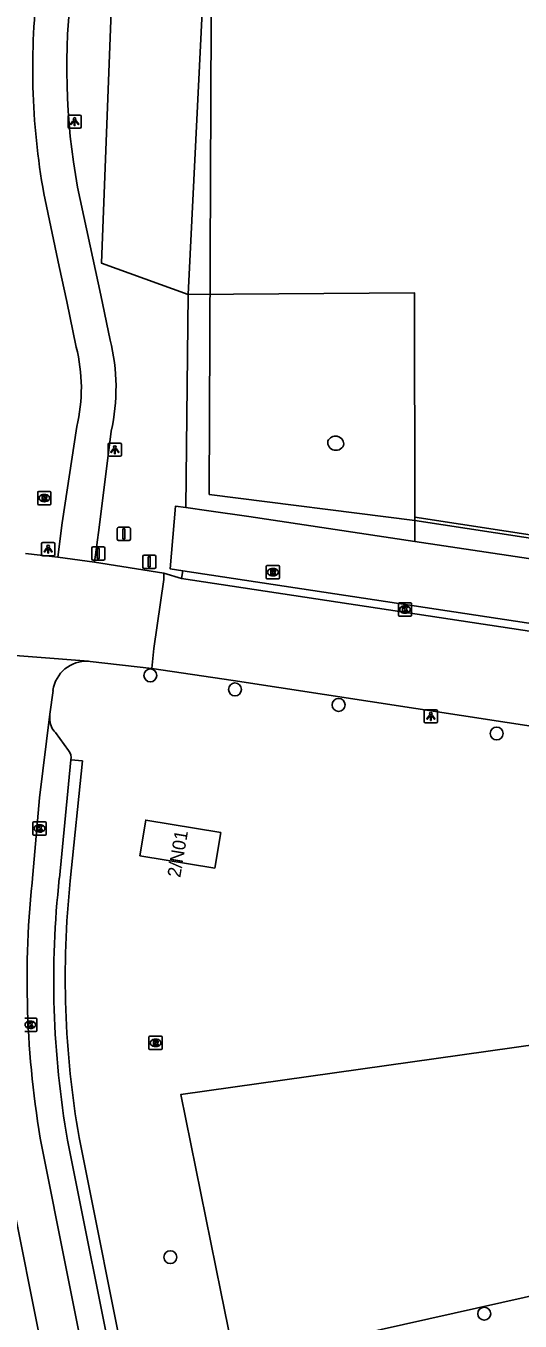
# Model space of a CAD drawing. Extents: x 160203 to 161526, y 379529 to 381797.
# Drawn here: x 160816.3 to 160853.7, y 380497.8 to 380595.6 of the extents above; entities that cross this region are included whole.
import ezdxf

# ---------------------------------------------------------------- set-up
doc = ezdxf.new("R2010")
doc.units = 0
for name, color, linetype in [('IMGEO_Boom', 7, 'Continuous'), ('IMGEO_Fietspad_open', 7, 'Continuous'), ('IMGEO_Gemengd_bos', 7, 'Continuous'), ('IMGEO_Hek', 7, 'Continuous'), ('IMGEO_Kolk', 7, 'Continuous'), ('IMGEO_Lichtpunt', 7, 'Continuous'), ('IMGEO_Loofbos', 7, 'Continuous'), ('IMGEO_Opslagtank', 7, 'Continuous'), ('IMGEO_Pand', 7, 'Continuous'), ('IMGEO_Pand_nummerreeks', 7, 'Continuous'), ('IMGEO_Parkeervlak_gesloten', 7, 'Continuous'), ('IMGEO_Parkeervlak_open', 7, 'Continuous'), ('IMGEO_Rijbaan_lokaal_gesloten', 7, 'Continuous'), ('IMGEO_Rijbaan_lokaal_open', 7, 'Continuous'), ('IMGEO_Rioolput', 7, 'Continuous'), ('IMGEO_Verkeersbordpaal', 7, 'Continuous'), ('IMGEO_Vlaggenmast', 7, 'Continuous'), ('IMGEO_Voetpad_open', 7, 'Continuous')]:
    doc.layers.add(name, color=color, linetype=linetype)

msp = doc.modelspace()

# ---------------------------------------------------------------- linework, layer by layer
at = {"layer": 'IMGEO_Boom'}
for centre in [(160825.731, 380546.573), (160832.132, 380545.511), (160839.97, 380544.344), (160851.927, 380542.182), (160827.24, 380502.618), (160850.985, 380498.346)]:
    msp.add_circle(centre, 0.489, dxfattribs=at)
at = {"layer": 'IMGEO_Fietspad_open'}
for points in [[(160820.125, 380571.38), (160819.419, 380574.816), (160818.832, 380577.453), (160817.677, 380582.969)], [(160822.69, 380571.911), (160821.975, 380575.301), (160821.373, 380578.101), (160820.223, 380583.465)], [(160818.72, 380555.51), (160819.05, 380558.09), (160820.171, 380565.369)], [(160821.515, 380555.129), (160821.858, 380557.745), (160822.774, 380565.019)]]:
    msp.add_lwpolyline(points, dxfattribs=at)
for centre, radius, start, end in [((160869.954, 380592.425), 53.126, 172.76167, 190.25321), ((160869.742, 380592.476), 50.332, 172.68835, 190.31381), ((160808.088, 380568.287), 15.045, 347.4561, 13.94048), ((160807.852, 380568.28), 12.658, 346.70262, 14.17429)]:
    msp.add_arc(centre, radius, start, end, dxfattribs=at)
at = {"layer": 'IMGEO_Gemengd_bos'}
for points in [[(160828.587, 380575.341), (160822.037, 380577.708), (160823.148, 380606.566), (160823.194, 380607.805)], [(160830.151, 380607.923), (160830.156, 380606.87), (160828.587, 380575.341)], [(160828.405, 380559.25), (160828.587, 380575.341)], [(160828.587, 380575.341), (160845.706, 380575.486), (160845.74, 380558.527)], [(160845.74, 380558.527), (160910.065, 380548.671), (160940.334, 380544.69)], [(160845.744, 380556.692), (160845.74, 380558.527)]]:
    msp.add_lwpolyline(points, dxfattribs=at)
at = {"layer": 'IMGEO_Hek'}
for points in [[(160830.403, 380613.941), (160830.181, 380560.25)], [(160845.741, 380558.276), (160830.181, 380560.25)], [(160964.899, 380552.777), (160964.896, 380551.38), (160959.504, 380551), (160940.157, 380543.996), (160899.412, 380550.147), (160882.829, 380552.68), (160868.014, 380554.875), (160845.741, 380558.276)], [(160855.926, 380500), (160832.145, 380494.674)]]:
    msp.add_lwpolyline(points, dxfattribs=at)
at = {"layer": 'IMGEO_Kolk'}
for p, q in [((160844.494, 380551.124), (160844.494, 380551.976)), ((160844.569, 380552.05), (160845.421, 380552.05)), ((160845.005, 380551.27), (160844.98, 380551.27)), ((160844.982, 380551.83), (160845.007, 380551.83)), ((160845.495, 380551.976), (160845.495, 380551.124)), ((160845.421, 380551.05), (160844.569, 380551.05)), ((160816.849, 380534.584), (160816.849, 380535.436)), ((160816.924, 380535.51), (160817.776, 380535.51)), ((160817.36, 380534.73), (160817.335, 380534.73)), ((160817.337, 380535.29), (160817.362, 380535.29)), ((160817.85, 380535.436), (160817.85, 380534.584)), ((160817.776, 380534.51), (160816.924, 380534.51)), ((160816.224, 380520.676), (160817.076, 380520.676)), ((160816.66, 380519.896), (160816.635, 380519.896)), ((160816.637, 380520.456), (160816.662, 380520.456)), ((160817.15, 380520.602), (160817.15, 380519.75)), ((160817.076, 380519.676), (160816.224, 380519.676))]:
    msp.add_line(p, q, dxfattribs=at)
for points in [[(160844.494, 380551.124), (160844.494, 380551.976)], [(160844.569, 380552.05), (160845.421, 380552.05)], [(160844.815, 380551.75), (160844.938, 380551.75), (160844.938, 380551.599), (160845.068, 380551.75), (160845.232, 380551.75), (160845.086, 380551.599), (160845.239, 380551.35), (160845.087, 380551.35), (160845.002, 380551.514), (160844.938, 380551.447), (160844.938, 380551.35), (160844.815, 380551.35), (160844.815, 380551.75)], [(160845.495, 380551.976), (160845.495, 380551.124)], [(160845.421, 380551.05), (160844.569, 380551.05)], [(160816.849, 380534.584), (160816.849, 380535.436)], [(160816.924, 380535.51), (160817.776, 380535.51)], [(160817.17, 380535.21), (160817.293, 380535.21), (160817.293, 380535.059), (160817.423, 380535.21), (160817.587, 380535.21), (160817.441, 380535.059), (160817.594, 380534.81), (160817.442, 380534.81), (160817.357, 380534.974), (160817.293, 380534.907), (160817.293, 380534.81), (160817.17, 380534.81), (160817.17, 380535.21)], [(160817.85, 380535.436), (160817.85, 380534.584)], [(160817.776, 380534.51), (160816.924, 380534.51)], [(160816.224, 380520.676), (160817.076, 380520.676)], [(160816.47, 380520.376), (160816.593, 380520.376), (160816.593, 380520.225), (160816.723, 380520.376), (160816.887, 380520.376), (160816.741, 380520.225), (160816.894, 380519.976), (160816.742, 380519.976), (160816.657, 380520.14), (160816.593, 380520.073), (160816.593, 380519.976), (160816.47, 380519.976), (160816.47, 380520.376)], [(160817.15, 380520.602), (160817.15, 380519.75)], [(160817.076, 380519.676), (160816.224, 380519.676)]]:
    msp.add_lwpolyline(points, dxfattribs=at)
for centre, start, end in [((160844.571, 380551.974), 91.55205, 178.44795), ((160844.571, 380551.974), 91.55205, 178.44795), ((160845.419, 380551.974), 1.55205, 88.44795), ((160845.419, 380551.974), 1.55205, 88.44795), ((160844.571, 380551.126), 181.55205, 268.44795), ((160844.571, 380551.126), 181.55205, 268.44795), ((160845.419, 380551.126), 271.55205, 358.44795), ((160845.419, 380551.126), 271.55205, 358.44795), ((160816.926, 380535.434), 91.55205, 178.44795), ((160816.926, 380535.434), 91.55205, 178.44795), ((160816.926, 380534.586), 181.55205, 268.44795), ((160816.926, 380534.586), 181.55205, 268.44795), ((160817.774, 380535.434), 1.55205, 88.44795), ((160817.774, 380535.434), 1.55205, 88.44795), ((160817.774, 380534.586), 271.55205, 358.44795), ((160817.774, 380534.586), 271.55205, 358.44795), ((160817.074, 380520.6), 1.55205, 88.44795), ((160817.074, 380520.6), 1.55205, 88.44795), ((160817.074, 380519.752), 271.55205, 358.44795), ((160817.074, 380519.752), 271.55205, 358.44795)]:
    msp.add_arc(centre, 0.0765, start, end, dxfattribs=at)
for centre, major_axis, ratio, start_param, end_param in [((160844.981, 380551.55), (-0.387, 0.002), 0.722429, 4.712389, 7.853982), ((160845.006, 380551.55), (-0.39, 0.002), 0.717154, 1.570796, 4.712389), ((160817.336, 380535.01), (-0.387, 0.002), 0.722429, 4.712389, 7.853982), ((160817.361, 380535.01), (-0.39, 0.002), 0.717154, 1.570796, 4.712389), ((160816.636, 380520.176), (-0.387, 0.002), 0.722429, 4.712389, 7.853982), ((160816.661, 380520.176), (-0.39, 0.002), 0.717154, 1.570796, 4.712389)]:
    msp.add_ellipse(centre, major_axis=major_axis, ratio=ratio, start_param=start_param, end_param=end_param, dxfattribs=at)
at = {"layer": 'IMGEO_Lichtpunt'}
for p, q in [((160819.503, 380588.813), (160819.503, 380588.006)), ((160819.503, 380588.813), (160819.503, 380588.006)), ((160820.405, 380588.908), (160819.597, 380588.908)), ((160820.405, 380588.908), (160819.597, 380588.908)), ((160820.499, 380588.006), (160820.499, 380588.813)), ((160820.499, 380588.006), (160820.499, 380588.813)), ((160819.597, 380587.912), (160820.405, 380587.912)), ((160819.597, 380587.912), (160820.405, 380587.912)), ((160822.547, 380564.029), (160822.547, 380563.222)), ((160822.547, 380564.029), (160822.547, 380563.222)), ((160823.449, 380564.124), (160822.641, 380564.124)), ((160823.449, 380564.124), (160822.641, 380564.124)), ((160823.543, 380563.222), (160823.543, 380564.029)), ((160823.543, 380563.222), (160823.543, 380564.029)), ((160822.641, 380563.128), (160823.449, 380563.128)), ((160822.641, 380563.128), (160823.449, 380563.128)), ((160817.502, 380556.516), (160817.502, 380555.709)), ((160817.502, 380556.516), (160817.502, 380555.709)), ((160818.404, 380556.611), (160817.596, 380556.611)), ((160818.404, 380556.611), (160817.596, 380556.611)), ((160818.498, 380555.709), (160818.498, 380556.516)), ((160818.498, 380555.709), (160818.498, 380556.516)), ((160817.596, 380555.615), (160818.404, 380555.615)), ((160817.596, 380555.615), (160818.404, 380555.615)), ((160846.448, 380543.881), (160846.448, 380543.074)), ((160846.448, 380543.881), (160846.448, 380543.074)), ((160847.35, 380543.976), (160846.542, 380543.976)), ((160847.35, 380543.976), (160846.542, 380543.976)), ((160847.444, 380543.074), (160847.444, 380543.881)), ((160847.444, 380543.074), (160847.444, 380543.881)), ((160846.542, 380542.98), (160847.35, 380542.98)), ((160846.542, 380542.98), (160847.35, 380542.98))]:
    msp.add_line(p, q, dxfattribs=at)
for points in [[(160819.877, 380588.477), (160819.916, 380588.449), (160819.728, 380588.187), (160819.69, 380588.214), (160819.877, 380588.477)], [(160819.979, 380588.429), (160820.026, 380588.429), (160820.026, 380588.107), (160819.979, 380588.107), (160819.979, 380588.429)], [(160820.089, 380588.449), (160820.127, 380588.476), (160820.314, 380588.214), (160820.275, 380588.186), (160820.089, 380588.449)], [(160822.921, 380563.693), (160822.96, 380563.665), (160822.772, 380563.403), (160822.734, 380563.43), (160822.921, 380563.693)], [(160823.023, 380563.645), (160823.07, 380563.645), (160823.07, 380563.323), (160823.023, 380563.323), (160823.023, 380563.645)], [(160823.133, 380563.665), (160823.171, 380563.692), (160823.358, 380563.43), (160823.319, 380563.402), (160823.133, 380563.665)], [(160817.876, 380556.18), (160817.915, 380556.152), (160817.727, 380555.89), (160817.689, 380555.917), (160817.876, 380556.18)], [(160817.978, 380556.132), (160818.025, 380556.132), (160818.025, 380555.81), (160817.978, 380555.81), (160817.978, 380556.132)], [(160818.088, 380556.152), (160818.126, 380556.179), (160818.313, 380555.917), (160818.274, 380555.889), (160818.088, 380556.152)], [(160846.822, 380543.545), (160846.861, 380543.517), (160846.673, 380543.255), (160846.635, 380543.282), (160846.822, 380543.545)], [(160846.924, 380543.497), (160846.971, 380543.497), (160846.971, 380543.175), (160846.924, 380543.175), (160846.924, 380543.497)], [(160847.034, 380543.517), (160847.072, 380543.544), (160847.259, 380543.282), (160847.22, 380543.254), (160847.034, 380543.517)]]:
    msp.add_lwpolyline(points, dxfattribs=at)
for centre in [(160820.002, 380588.611), (160823.046, 380563.827), (160818.001, 380556.314), (160846.947, 380543.679)]:
    msp.add_circle(centre, 0.0994, dxfattribs=at)
for centre, start, end in [((160819.597, 380588.813), 90, 180), ((160819.597, 380588.813), 90, 180), ((160820.405, 380588.813), 0, 90), ((160820.405, 380588.813), 0, 90), ((160819.597, 380588.006), 180, 270), ((160819.597, 380588.006), 180, 270), ((160820.405, 380588.006), 270, 0), ((160820.405, 380588.006), 270, 360), ((160822.641, 380564.029), 90, 180), ((160822.641, 380564.029), 90, 180), ((160823.449, 380564.029), 0, 90), ((160823.449, 380564.029), 0, 90), ((160822.641, 380563.222), 180, 270), ((160822.641, 380563.222), 180, 270), ((160823.449, 380563.222), 270, 0), ((160823.449, 380563.222), 270, 360), ((160817.596, 380556.516), 90, 180), ((160817.596, 380556.516), 90, 180), ((160818.404, 380556.516), 0, 90), ((160818.404, 380556.516), 0, 90), ((160817.596, 380555.709), 180, 270), ((160817.596, 380555.709), 180, 270), ((160818.404, 380555.709), 270, 0), ((160818.404, 380555.709), 270, 360), ((160846.542, 380543.881), 90, 180), ((160846.542, 380543.881), 90, 180), ((160847.35, 380543.881), 0, 90), ((160847.35, 380543.881), 0, 90), ((160846.542, 380543.074), 180, 270), ((160846.542, 380543.074), 180, 270), ((160847.35, 380543.074), 270, 0), ((160847.35, 380543.074), 270, 360)]:
    msp.add_arc(centre, 0.0946, start, end, dxfattribs=at)
at = {"layer": 'IMGEO_Loofbos'}
for points in [[(160832.145, 380494.674), (160831.064, 380500), (160828.037, 380514.908), (160874.529, 380521.462), (160876.82, 380510.174), (160917.453, 380518.109), (160923.009, 380526.579), (160955.011, 380521.483), (160954.687, 380518.782)], [(160832.145, 380494.674), (160855.926, 380500), (160951.456, 380519.19), (160951.518, 380519.182), (160951.934, 380519.13)]]:
    msp.add_lwpolyline(points, dxfattribs=at)
at = {"layer": 'IMGEO_Opslagtank'}
for centre, radius, start, end in [((160839.769, 380564.197), 0.62, 171.68625, 347.67097), ((160839.734, 380564.002), 0.644, 5.56869, 153.78853)]:
    msp.add_arc(centre, radius, start, end, dxfattribs=at)
at = {"layer": 'IMGEO_Pand'}
msp.add_lwpolyline([(160830.608, 380532.01), (160824.942, 380532.951), (160825.388, 380535.638), (160831.054, 380534.697), (160830.608, 380532.01)], dxfattribs=at)
at = {"layer": 'IMGEO_Parkeervlak_gesloten'}
for points in [[(160828.18, 380554.482), (160827.221, 380554.627), (160827.637, 380559.36), (160828.405, 380559.25)], [(160828.405, 380559.25), (160830.154, 380559), (160833.175, 380558.569), (160845.744, 380556.692)], [(160940.686, 380542.511), (160845.744, 380556.692)]]:
    msp.add_lwpolyline(points, dxfattribs=at)
at = {"layer": 'IMGEO_Parkeervlak_open'}
for points in [[(160818.114, 380543.649), (160818.123, 380543.336)], [(160818.553, 380542.257), (160819.548, 380540.908)]]:
    msp.add_lwpolyline(points, dxfattribs=at)
for centre, radius, start, end in [((160819.547, 380543.278), 1.425, 177.68496, 225.7713), ((160818.773, 380540.337), 0.963, 350.68548, 36.38347)]:
    msp.add_arc(centre, radius, start, end, dxfattribs=at)
at = {"layer": 'IMGEO_Rijbaan_lokaal_gesloten'}
for points in [[(160818.72, 380555.51), (160816.276, 380555.793)], [(160821.515, 380555.129), (160818.72, 380555.51)], [(160826.75, 380554.296), (160821.515, 380555.129)], [(160825.841, 380547.097), (160825.987, 380548.612), (160826.76, 380553.818), (160826.75, 380554.296)], [(160812.565, 380548.307), (160821.039, 380547.637)], [(160825.841, 380547.097), (160821.176, 380547.625), (160821.039, 380547.637)], [(160818.366, 380545.438), (160818.114, 380543.649)], [(160816.849, 380531.541), (160817.348, 380537.309), (160818.114, 380543.649)], [(160814.424, 380511.244), (160818.287, 380491.97), (160848.829, 380339.603)], [(160851.769, 380340.218), (160821.234, 380492.423), (160817.512, 380510.978)]]:
    msp.add_lwpolyline(points, dxfattribs=at)
for centre, radius, start, end in [((160820.893, 380545.09), 2.551, 86.72391, 172.16238), ((160888.578, 380523.562), 72.171, 173.6522, 190.04122)]:
    msp.add_arc(centre, radius, start, end, dxfattribs=at)
at = {"layer": 'IMGEO_Rijbaan_lokaal_open'}
for points in [[(160826.75, 380554.296), (160828.089, 380553.895)], [(160828.089, 380553.895), (160828.18, 380554.482)], [(160828.18, 380554.482), (161000, 380528.513), (161026.173, 380524.441)], [(160828.089, 380553.895), (161000, 380527.913), (161026.094, 380523.879)], [(160965.031, 380525.91), (160911.436, 380534.021), (160831.991, 380546.196), (160825.841, 380547.097)]]:
    msp.add_lwpolyline(points, dxfattribs=at)
at = {"layer": 'IMGEO_Rioolput'}
for p, q in [((160817.208, 380559.544), (160817.208, 380560.396)), ((160817.283, 380560.47), (160818.135, 380560.47)), ((160817.696, 380560.25), (160817.721, 380560.25)), ((160818.209, 380560.396), (160818.209, 380559.544)), ((160818.135, 380559.47), (160817.283, 380559.47)), ((160817.719, 380559.69), (160817.694, 380559.69)), ((160834.5, 380553.944), (160834.5, 380554.796)), ((160834.575, 380554.87), (160835.427, 380554.87)), ((160834.988, 380554.65), (160835.013, 380554.65)), ((160835.501, 380554.796), (160835.501, 380553.944)), ((160835.427, 380553.87), (160834.575, 380553.87)), ((160835.011, 380554.09), (160834.986, 380554.09)), ((160825.627, 380518.383), (160825.627, 380519.235)), ((160825.702, 380519.309), (160826.554, 380519.309)), ((160826.115, 380519.089), (160826.14, 380519.089)), ((160826.628, 380519.235), (160826.628, 380518.383)), ((160826.554, 380518.309), (160825.702, 380518.309)), ((160826.138, 380518.529), (160826.113, 380518.529))]:
    msp.add_line(p, q, dxfattribs=at)
for points in [[(160817.208, 380559.544), (160817.208, 380560.396)], [(160817.283, 380560.47), (160818.135, 380560.47)], [(160817.797, 380560.168), (160817.545, 380560.17), (160817.545, 380559.77)], [(160817.723, 380560.089), (160817.669, 380560.089), (160817.669, 380560.008)], [(160817.669, 380560.008), (160817.721, 380560.008)], [(160818.209, 380560.396), (160818.209, 380559.544)], [(160818.135, 380559.47), (160817.283, 380559.47)], [(160817.545, 380559.77), (160817.669, 380559.77), (160817.669, 380559.932), (160817.68, 380559.932)], [(160817.727, 380559.903), (160817.798, 380559.77), (160817.938, 380559.77), (160817.873, 380559.896)], [(160834.5, 380553.944), (160834.5, 380554.796)], [(160834.575, 380554.87), (160835.427, 380554.87)], [(160835.089, 380554.568), (160834.837, 380554.57), (160834.837, 380554.17)], [(160834.837, 380554.17), (160834.961, 380554.17), (160834.961, 380554.332), (160834.972, 380554.332)], [(160835.015, 380554.489), (160834.961, 380554.489), (160834.961, 380554.408)], [(160834.961, 380554.408), (160835.013, 380554.408)], [(160835.019, 380554.303), (160835.09, 380554.17), (160835.23, 380554.17), (160835.165, 380554.296)], [(160835.501, 380554.796), (160835.501, 380553.944)], [(160835.427, 380553.87), (160834.575, 380553.87)], [(160825.627, 380518.383), (160825.627, 380519.235)], [(160825.702, 380519.309), (160826.554, 380519.309)], [(160826.216, 380519.007), (160825.964, 380519.009), (160825.964, 380518.609)], [(160826.142, 380518.928), (160826.088, 380518.928), (160826.088, 380518.847)], [(160826.628, 380519.235), (160826.628, 380518.383)], [(160826.554, 380518.309), (160825.702, 380518.309)], [(160825.964, 380518.609), (160826.088, 380518.609), (160826.088, 380518.771), (160826.099, 380518.771)], [(160826.088, 380518.847), (160826.14, 380518.847)], [(160826.146, 380518.742), (160826.217, 380518.609), (160826.357, 380518.609), (160826.292, 380518.735)]]:
    msp.add_lwpolyline(points, dxfattribs=at)
for centre, radius, start, end in [((160817.285, 380560.394), 0.0765, 91.55205, 178.44795), ((160817.285, 380560.394), 0.0765, 91.55205, 178.44795), ((160817.705, 380560.197), 0.19, 274.7715, 282.96867), ((160817.729, 380559.993), 0.0964, 77.00612, 93.18647), ((160817.743, 380560.05), 0.0378, 276.66336, 79.67722), ((160817.796, 380560.058), 0.109, 350.36119, 89.41601), ((160817.794, 380560.058), 0.112, 277.58423, 350.98172), ((160818.133, 380560.394), 0.0765, 1.55205, 88.44795), ((160818.133, 380560.394), 0.0765, 1.55205, 88.44795), ((160817.285, 380559.546), 0.0765, 181.55205, 268.44795), ((160817.285, 380559.546), 0.0765, 181.55205, 268.44795), ((160817.679, 380559.879), 0.0533, 26.02933, 88.69889), ((160817.778, 380559.843), 0.108, 29.51342, 73.79051), ((160818.133, 380559.546), 0.0765, 271.55205, 358.44795), ((160818.133, 380559.546), 0.0765, 271.55205, 358.44795), ((160834.577, 380554.794), 0.0765, 91.55205, 178.44795), ((160834.577, 380554.794), 0.0765, 91.55205, 178.44795), ((160834.971, 380554.279), 0.0533, 26.02933, 88.69889), ((160834.997, 380554.597), 0.19, 274.7715, 282.96867), ((160835.021, 380554.393), 0.0964, 77.00612, 93.18647), ((160835.035, 380554.45), 0.0378, 276.66336, 79.67722), ((160835.088, 380554.458), 0.109, 350.36119, 89.41601), ((160835.086, 380554.458), 0.112, 277.58423, 350.98172), ((160835.07, 380554.243), 0.108, 29.51342, 73.79051), ((160835.425, 380554.794), 0.0765, 1.55205, 88.44795), ((160835.425, 380554.794), 0.0765, 1.55205, 88.44795), ((160834.577, 380553.946), 0.0765, 181.55205, 268.44795), ((160834.577, 380553.946), 0.0765, 181.55205, 268.44795), ((160835.425, 380553.946), 0.0765, 271.55205, 358.44795), ((160835.425, 380553.946), 0.0765, 271.55205, 358.44795), ((160825.704, 380519.233), 0.0765, 91.55205, 178.44795), ((160825.704, 380519.233), 0.0765, 91.55205, 178.44795), ((160826.148, 380518.832), 0.0964, 77.00612, 93.18647), ((160826.162, 380518.889), 0.0378, 276.66336, 79.67722), ((160826.215, 380518.897), 0.109, 350.36119, 89.41601), ((160826.552, 380519.233), 0.0765, 1.55205, 88.44795), ((160826.552, 380519.233), 0.0765, 1.55205, 88.44795), ((160825.704, 380518.385), 0.0765, 181.55205, 268.44795), ((160825.704, 380518.385), 0.0765, 181.55205, 268.44795), ((160826.098, 380518.718), 0.0533, 26.02933, 88.69889), ((160826.124, 380519.036), 0.19, 274.7715, 282.96867), ((160826.213, 380518.897), 0.112, 277.58423, 350.98172), ((160826.197, 380518.682), 0.108, 29.51342, 73.79051), ((160826.552, 380518.385), 0.0765, 271.55205, 358.44795), ((160826.552, 380518.385), 0.0765, 271.55205, 358.44795)]:
    msp.add_arc(centre, radius, start, end, dxfattribs=at)
for centre, major_axis, ratio, start_param, end_param in [((160817.695, 380559.97), (-0.387, 0.002), 0.722429, 4.712389, 7.853982), ((160817.72, 380559.97), (-0.39, 0.002), 0.717154, 1.570796, 4.712389), ((160834.987, 380554.37), (-0.387, 0.002), 0.722429, 4.712389, 7.853982), ((160835.012, 380554.37), (-0.39, 0.002), 0.717154, 1.570796, 4.712389), ((160826.114, 380518.809), (-0.387, 0.002), 0.722429, 4.712389, 7.853982), ((160826.139, 380518.809), (-0.39, 0.002), 0.717154, 1.570796, 4.712389)]:
    msp.add_ellipse(centre, major_axis=major_axis, ratio=ratio, start_param=start_param, end_param=end_param, dxfattribs=at)
at = {"layer": 'IMGEO_Verkeersbordpaal'}
for p, q in [((160821.296, 380555.383), (160821.296, 380556.183)), ((160821.296, 380556.183), (160821.296, 380555.383)), ((160821.396, 380556.283), (160822.186, 380556.283)), ((160822.186, 380556.283), (160821.396, 380556.283)), ((160822.286, 380556.183), (160822.286, 380555.383)), ((160822.286, 380555.383), (160822.286, 380556.183)), ((160822.186, 380555.283), (160821.396, 380555.283)), ((160821.396, 380555.283), (160822.186, 380555.283))]:
    msp.add_line(p, q, dxfattribs=at)
msp.add_lwpolyline([(160821.716, 380556.158), (160821.866, 380556.158), (160821.866, 380555.408), (160821.716, 380555.408), (160821.716, 380556.158)], dxfattribs=at)
for centre, start, end in [((160821.396, 380556.183), 90, 180), ((160821.396, 380556.183), 90, 180), ((160822.186, 380556.183), 0, 90), ((160822.186, 380556.183), 360, 90), ((160821.396, 380555.383), 180, 270), ((160821.396, 380555.383), 180, 270), ((160822.186, 380555.383), 270, 0), ((160822.186, 380555.383), 270, 0)]:
    msp.add_arc(centre, 0.1, start, end, dxfattribs=at)
at = {"layer": 'IMGEO_Vlaggenmast'}
for p, q in [((160823.229, 380556.861), (160823.229, 380557.661)), ((160823.229, 380557.661), (160823.229, 380556.861)), ((160823.329, 380557.761), (160824.119, 380557.761)), ((160824.119, 380557.761), (160823.329, 380557.761)), ((160824.219, 380557.661), (160824.219, 380556.861)), ((160824.219, 380556.861), (160824.219, 380557.661)), ((160824.119, 380556.761), (160823.329, 380556.761)), ((160823.329, 380556.761), (160824.119, 380556.761)), ((160825.156, 380554.756), (160825.156, 380555.556)), ((160825.156, 380555.556), (160825.156, 380554.756)), ((160825.256, 380555.656), (160826.046, 380555.656)), ((160826.046, 380555.656), (160825.256, 380555.656)), ((160826.146, 380555.556), (160826.146, 380554.756)), ((160826.146, 380554.756), (160826.146, 380555.556)), ((160826.046, 380554.656), (160825.256, 380554.656)), ((160825.256, 380554.656), (160826.046, 380554.656))]:
    msp.add_line(p, q, dxfattribs=at)
for points in [[(160823.649, 380557.636), (160823.799, 380557.636), (160823.799, 380556.886), (160823.649, 380556.886), (160823.649, 380557.636)], [(160825.576, 380555.531), (160825.726, 380555.531), (160825.726, 380554.781), (160825.576, 380554.781), (160825.576, 380555.531)]]:
    msp.add_lwpolyline(points, dxfattribs=at)
for centre, start, end in [((160823.329, 380557.661), 90, 180), ((160823.329, 380557.661), 90, 180), ((160824.119, 380557.661), 0, 90), ((160824.119, 380557.661), 360, 90), ((160823.329, 380556.861), 180, 270), ((160823.329, 380556.861), 180, 270), ((160824.119, 380556.861), 270, 0), ((160824.119, 380556.861), 270, 0), ((160825.256, 380555.556), 90, 180), ((160825.256, 380555.556), 90, 180), ((160826.046, 380555.556), 0, 90), ((160826.046, 380555.556), 360, 90), ((160825.256, 380554.756), 180, 270), ((160825.256, 380554.756), 180, 270), ((160826.046, 380554.756), 270, 0), ((160826.046, 380554.756), 270, 0)]:
    msp.add_arc(centre, 0.1, start, end, dxfattribs=at)
at = {"layer": 'IMGEO_Voetpad_open'}
for points in [[(160819.723, 380540.181), (160818.845, 380531.241)], [(160819.723, 380540.181), (160820.588, 380540.108), (160819.672, 380531.052)], [(160819.469, 380511.448), (160823.223, 380492.728), (160853.643, 380341.04)], [(160820.338, 380511.651), (160824.092, 380492.861)]]:
    msp.add_lwpolyline(points, dxfattribs=at)
for centre, radius, start, end in [((160888.563, 380523.533), 70.143, 173.69073, 189.92072), ((160889.682, 380523.743), 70.391, 174.04027, 189.8919)]:
    msp.add_arc(centre, radius, start, end, dxfattribs=at)

# ---------------------------------------------------------------- texts
at = {"layer": 'IMGEO_Pand_nummerreeks'}
msp.add_text('2/N01', height=1, rotation=80.4399, dxfattribs=at).set_placement((160827.991, 380531.254))

doc.saveas('drawing.dxf')
